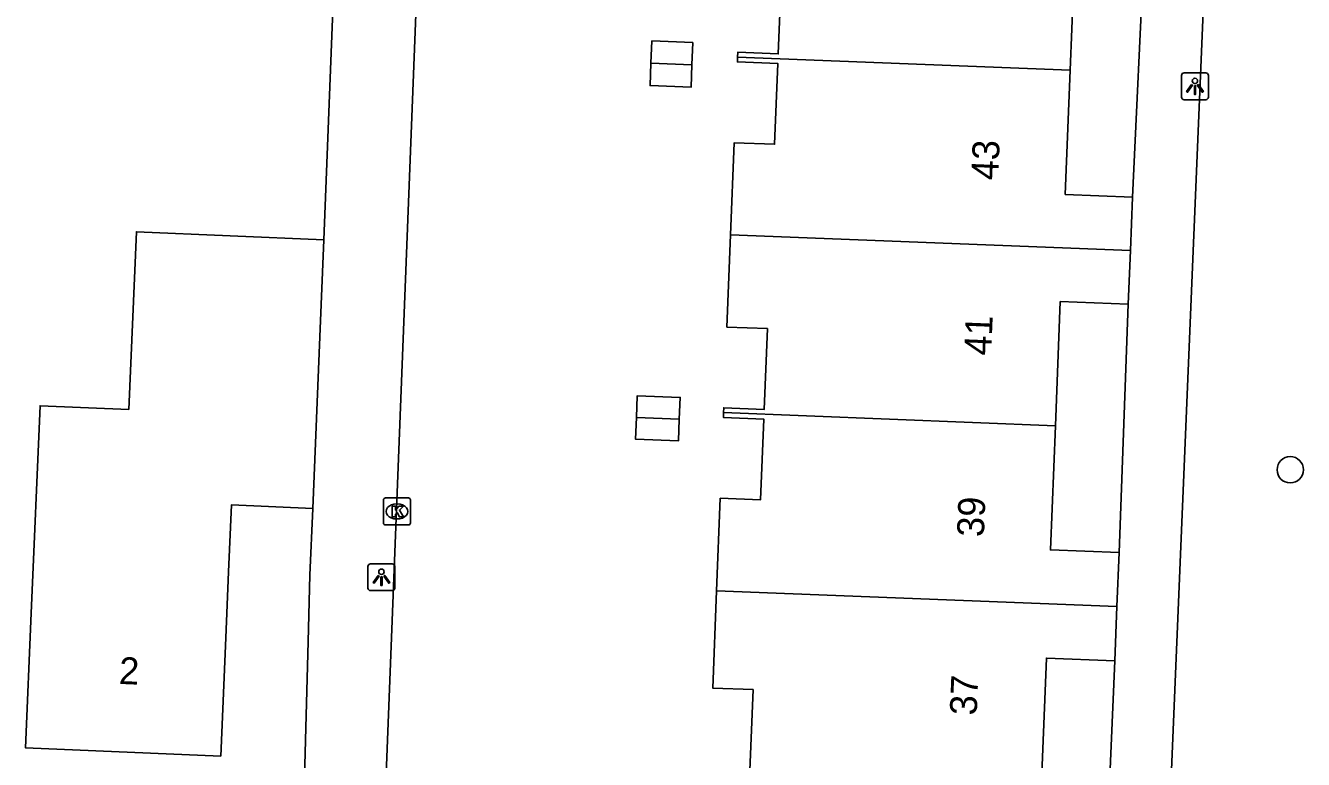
# Model space of a CAD drawing. Extents: x 160787 to 161428, y 386828 to 387483.
# Drawn here: x 160914.17 to 160961.57, y 387090.27 to 387117.52 of the extents above; entities that cross this region are included whole.
import ezdxf

# ---------------------------------------------------------------- set-up
doc = ezdxf.new("R2010")
doc.units = 0
for name, color, linetype in [('IMGEO_Boom', 7, 'Continuous'), ('IMGEO_Kolk', 7, 'Continuous'), ('IMGEO_Lichtpunt', 7, 'Continuous'), ('IMGEO_Pand', 7, 'Continuous'), ('IMGEO_Pand_nummerreeks', 7, 'Continuous'), ('IMGEO_Voetpad_open', 7, 'Continuous')]:
    doc.layers.add(name, color=color, linetype=linetype)

msp = doc.modelspace()

# ---------------------------------------------------------------- linework, layer by layer
at = {"layer": 'IMGEO_Boom'}
msp.add_circle((160961.085, 387101.027), 0.489, dxfattribs=at)
at = {"layer": 'IMGEO_Kolk'}
for p, q in [((160927.449, 387099.053), (160927.449, 387099.905)), ((160927.524, 387099.979), (160928.376, 387099.979)), ((160927.937, 387099.759), (160927.962, 387099.759)), ((160928.45, 387099.905), (160928.45, 387099.053)), ((160927.96, 387099.199), (160927.935, 387099.199)), ((160928.376, 387098.979), (160927.524, 387098.979))]:
    msp.add_line(p, q, dxfattribs=at)
for points in [[(160927.449, 387099.053), (160927.449, 387099.905)], [(160927.524, 387099.979), (160928.376, 387099.979)], [(160927.77, 387099.679), (160927.893, 387099.679), (160927.893, 387099.528), (160928.023, 387099.679), (160928.187, 387099.679), (160928.041, 387099.528), (160928.194, 387099.279), (160928.042, 387099.279), (160927.957, 387099.443), (160927.893, 387099.376), (160927.893, 387099.279), (160927.77, 387099.279), (160927.77, 387099.679)], [(160928.45, 387099.905), (160928.45, 387099.053)], [(160928.376, 387098.979), (160927.524, 387098.979)]]:
    msp.add_lwpolyline(points, dxfattribs=at)
for centre, start, end in [((160927.526, 387099.903), 91.552, 178.448), ((160927.526, 387099.903), 91.552, 178.448), ((160928.374, 387099.903), 1.552, 88.448), ((160928.374, 387099.903), 1.552, 88.448), ((160927.526, 387099.055), 181.552, 268.448), ((160927.526, 387099.055), 181.552, 268.448), ((160928.374, 387099.055), 271.552, 358.448), ((160928.374, 387099.055), 271.552, 358.448)]:
    msp.add_arc(centre, 0.0765, start, end, dxfattribs=at)
for centre, major_axis, ratio, start_param, end_param in [((160927.936, 387099.479), (-0.387, 0.002), 0.722429, 4.712389, 7.853982), ((160927.961, 387099.479), (-0.39, 0.002), 0.717154, 1.570796, 4.712389)]:
    msp.add_ellipse(centre, major_axis=major_axis, ratio=ratio, start_param=start_param, end_param=end_param, dxfattribs=at)
at = {"layer": 'IMGEO_Lichtpunt'}
for p, q in [((160957.052, 387115.664), (160957.052, 387114.857)), ((160957.052, 387115.664), (160957.052, 387114.857)), ((160957.954, 387115.759), (160957.146, 387115.759)), ((160957.954, 387115.759), (160957.146, 387115.759)), ((160958.048, 387114.857), (160958.048, 387115.664)), ((160958.048, 387114.857), (160958.048, 387115.664)), ((160957.146, 387114.763), (160957.954, 387114.763)), ((160957.146, 387114.763), (160957.954, 387114.763)), ((160926.876, 387097.441), (160926.876, 387096.634)), ((160926.876, 387097.441), (160926.876, 387096.634)), ((160927.778, 387097.536), (160926.97, 387097.536)), ((160927.778, 387097.536), (160926.97, 387097.536)), ((160927.872, 387096.634), (160927.872, 387097.441)), ((160927.872, 387096.634), (160927.872, 387097.441)), ((160926.97, 387096.54), (160927.778, 387096.54)), ((160926.97, 387096.54), (160927.778, 387096.54))]:
    msp.add_line(p, q, dxfattribs=at)
for points in [[(160957.426, 387115.328), (160957.465, 387115.3), (160957.277, 387115.038), (160957.239, 387115.065), (160957.426, 387115.328)], [(160957.638, 387115.3), (160957.676, 387115.327), (160957.863, 387115.065), (160957.824, 387115.037), (160957.638, 387115.3)], [(160957.528, 387115.28), (160957.575, 387115.28), (160957.575, 387114.958), (160957.528, 387114.958), (160957.528, 387115.28)], [(160927.25, 387097.105), (160927.289, 387097.077), (160927.101, 387096.815), (160927.063, 387096.842), (160927.25, 387097.105)], [(160927.352, 387097.057), (160927.399, 387097.057), (160927.399, 387096.735), (160927.352, 387096.735), (160927.352, 387097.057)], [(160927.462, 387097.077), (160927.5, 387097.104), (160927.687, 387096.842), (160927.648, 387096.814), (160927.462, 387097.077)]]:
    msp.add_lwpolyline(points, dxfattribs=at)
for centre in [(160957.551, 387115.462), (160927.375, 387097.239)]:
    msp.add_circle(centre, 0.0994, dxfattribs=at)
for centre, start, end in [((160957.146, 387115.664), 90, 180), ((160957.146, 387115.664), 90, 180), ((160957.954, 387115.664), 0, 90), ((160957.954, 387115.664), 0, 90), ((160957.146, 387114.857), 180, 270), ((160957.146, 387114.857), 180, 270), ((160957.954, 387114.857), 270, 0), ((160957.954, 387114.857), 270, 360), ((160926.97, 387097.441), 90, 180), ((160926.97, 387097.441), 90, 180), ((160927.778, 387097.441), 0, 90), ((160927.778, 387097.441), 0, 90), ((160926.97, 387096.634), 180, 270), ((160926.97, 387096.634), 180, 270), ((160927.778, 387096.634), 270, 0), ((160927.778, 387096.634), 270, 360)]:
    msp.add_arc(centre, 0.0946, start, end, dxfattribs=at)
at = {"layer": 'IMGEO_Pand'}
for points in [[(160940.847, 387122.928), (160940.712, 387119.523), (160942.211, 387119.463), (160942.093, 387116.466), (160940.594, 387116.525), (160940.587, 387116.345)], [(160952.921, 387115.858), (160953.103, 387120.471), (160955.663, 387120.37)], [(160938.892, 387116.056), (160938.925, 387116.885), (160937.405, 387116.945), (160937.373, 387116.116)], [(160940.587, 387116.345), (160940.58, 387116.165), (160942.079, 387116.106), (160941.96, 387113.108), (160940.462, 387113.167), (160940.327, 387109.746)], [(160940.587, 387116.345), (160952.921, 387115.858)], [(160937.373, 387116.116), (160937.34, 387115.286), (160938.859, 387115.226), (160938.892, 387116.056)], [(160938.892, 387116.056), (160937.373, 387116.116)], [(160952.921, 387115.858), (160952.739, 387111.247), (160955.234, 387111.149)], [(160955.234, 387111.149), (160955.155, 387109.16)], [(160925.236, 387109.559), (160918.288, 387109.859), (160918.004, 387103.265), (160914.712, 387103.404), (160914.386, 387095.698), (160914.174, 387090.702), (160921.416, 387090.395), (160921.602, 387094.786), (160921.706, 387097.24), (160921.811, 387099.721), (160924.824, 387099.594)], [(160940.327, 387109.746), (160940.192, 387106.326), (160941.69, 387106.266), (160941.572, 387103.269), (160940.073, 387103.328), (160940.066, 387103.148)], [(160940.327, 387109.746), (160955.155, 387109.16)], [(160924.824, 387099.594), (160925.093, 387105.962), (160925.236, 387109.559)], [(160955.155, 387109.16), (160955.077, 387107.172)], [(160955.077, 387107.172), (160952.554, 387107.272), (160952.372, 387102.662)], [(160938.424, 387102.903), (160938.456, 387103.71), (160936.863, 387103.773), (160936.831, 387102.966)], [(160939.805, 387096.532), (160939.941, 387099.97), (160941.439, 387099.911), (160941.558, 387102.909), (160940.059, 387102.968), (160940.066, 387103.148)], [(160940.066, 387103.148), (160952.372, 387102.662)], [(160936.831, 387102.966), (160936.799, 387102.16), (160938.392, 387102.097), (160938.424, 387102.903)], [(160938.424, 387102.903), (160936.831, 387102.966)], [(160952.372, 387102.662), (160952.19, 387098.054), (160954.737, 387097.953)], [(160954.737, 387097.953), (160954.658, 387095.945)], [(160939.805, 387096.532), (160939.663, 387092.924), (160941.163, 387092.864), (160941.044, 387089.867)], [(160954.658, 387095.945), (160939.805, 387096.532)], [(160954.658, 387095.945), (160954.579, 387093.934)], [(160954.579, 387093.934), (160952.041, 387094.035), (160951.859, 387089.44)]]:
    msp.add_lwpolyline(points, dxfattribs=at)
at = {"layer": 'IMGEO_Voetpad_open'}
for points in [[(160956.038, 387074.481), (160958.558, 387134.926)], [(160927.452, 387087.186), (160929.117, 387129.975)], [(160955.663, 387120.37), (160955.234, 387111.149)], [(160925.236, 387109.559), (160925.577, 387118.089)], [(160955.077, 387107.172), (160954.737, 387097.953)], [(160924.453, 387087.312), (160924.652, 387094.655), (160924.719, 387097.113), (160924.824, 387099.594)], [(160954.579, 387093.934), (160954.185, 387084.747)]]:
    msp.add_lwpolyline(points, dxfattribs=at)

# ---------------------------------------------------------------- texts
at = {"layer": 'IMGEO_Pand_nummerreeks'}
for s, rotation, p in [('43', 87.7084, (160950.25, 387111.762)), ('41', 87.7084, (160949.99, 387105.254)), ('39', 87.7084, (160949.72, 387098.52)), ('2', 357.5707, (160917.625, 387093.079)), ('37', 87.7084, (160949.454, 387091.899))]:
    msp.add_text(s, height=1, rotation=rotation, dxfattribs=at).set_placement(p)

doc.saveas('drawing.dxf')
